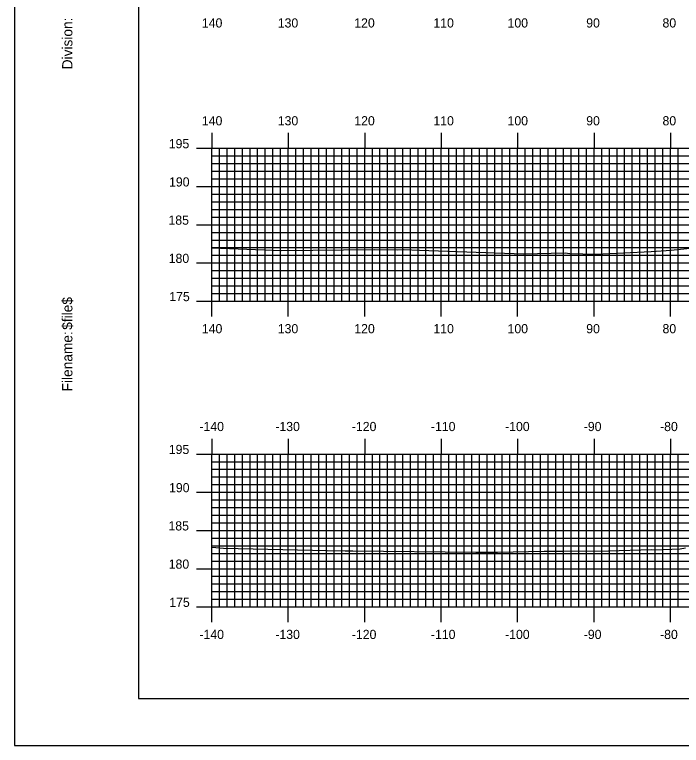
# Model space of a CAD drawing. Extents: x 1823573 to 1823916, y 442591 to 442811.
# Drawn here: x 1823572.5 to 1823659.7, y 442590.5 to 442686.2 of the extents above; entities that cross this region are included whole.
import ezdxf

# ---------------------------------------------------------------- set-up
doc = ezdxf.new("R2010")
doc.units = 0
for name, color, linetype in [('BORDER', 7, 'Continuous'), ('H_V ANNOTATION', 7, 'Continuous'), ('MAJOR', 7, 'Continuous'), ('MINOR', 7, 'Continuous'), ('PLOT BOUNDARY', 7, 'Continuous'), ('S_Roadway_Centerline', 7, 'Continuous')]:
    doc.layers.add(name, color=color, linetype=linetype)

msp = doc.modelspace()

# ---------------------------------------------------------------- linework, layer by layer
at = {"layer": 'BORDER'}
msp.add_lwpolyline([(1823588.709, 442596.665), (1823908.709, 442596.665), (1823908.709, 442806.665), (1823588.709, 442806.665)], close=True, dxfattribs=at)
at = {"layer": 'MAJOR'}
for p, q in [((1823598.309, 442670.669), (1823598.309, 442668.665)), ((1823608.309, 442670.669), (1823608.309, 442668.665)), ((1823618.309, 442670.669), (1823618.309, 442668.665)), ((1823628.309, 442670.669), (1823628.309, 442668.665)), ((1823638.309, 442670.669), (1823638.309, 442668.665)), ((1823648.309, 442670.669), (1823648.309, 442668.665)), ((1823658.309, 442670.669), (1823658.309, 442668.665)), ((1823596.305, 442668.665), (1823598.309, 442668.665)), ((1823598.309, 442668.665), (1823878.309, 442668.665)), ((1823598.309, 442648.665), (1823598.309, 442668.665)), ((1823598.309, 442648.665), (1823598.309, 442668.665)), ((1823598.309, 442668.665), (1823878.309, 442668.665)), ((1823608.309, 442648.665), (1823608.309, 442668.665)), ((1823618.309, 442648.665), (1823618.309, 442668.665)), ((1823628.309, 442648.665), (1823628.309, 442668.665)), ((1823638.309, 442648.665), (1823638.309, 442668.665)), ((1823648.309, 442648.665), (1823648.309, 442668.665)), ((1823658.309, 442648.665), (1823658.309, 442668.665)), ((1823596.305, 442663.665), (1823598.309, 442663.665)), ((1823598.309, 442663.665), (1823878.309, 442663.665)), ((1823596.305, 442658.665), (1823598.309, 442658.665)), ((1823598.309, 442658.665), (1823878.309, 442658.665)), ((1823596.305, 442653.665), (1823598.309, 442653.665)), ((1823598.309, 442653.665), (1823878.309, 442653.665)), ((1823596.305, 442648.665), (1823598.309, 442648.665)), ((1823598.309, 442648.665), (1823878.309, 442648.665)), ((1823598.309, 442648.665), (1823878.309, 442648.665)), ((1823598.309, 442646.661), (1823598.309, 442648.665)), ((1823608.309, 442646.661), (1823608.309, 442648.665)), ((1823618.309, 442646.661), (1823618.309, 442648.665)), ((1823628.309, 442646.661), (1823628.309, 442648.665)), ((1823638.309, 442646.661), (1823638.309, 442648.665)), ((1823648.309, 442646.661), (1823648.309, 442648.665)), ((1823658.309, 442646.661), (1823658.309, 442648.665)), ((1823598.309, 442630.669), (1823598.309, 442628.665)), ((1823608.309, 442630.669), (1823608.309, 442628.665)), ((1823618.309, 442630.669), (1823618.309, 442628.665)), ((1823628.309, 442630.669), (1823628.309, 442628.665)), ((1823638.309, 442630.669), (1823638.309, 442628.665)), ((1823648.309, 442630.669), (1823648.309, 442628.665)), ((1823658.309, 442630.669), (1823658.309, 442628.665)), ((1823596.305, 442628.665), (1823598.309, 442628.665)), ((1823598.309, 442628.665), (1823738.309, 442628.665)), ((1823598.309, 442608.665), (1823598.309, 442628.665)), ((1823598.309, 442608.665), (1823598.309, 442628.665)), ((1823598.309, 442628.665), (1823738.309, 442628.665)), ((1823608.309, 442608.665), (1823608.309, 442628.665)), ((1823618.309, 442608.665), (1823618.309, 442628.665)), ((1823628.309, 442608.665), (1823628.309, 442628.665)), ((1823638.309, 442608.665), (1823638.309, 442628.665)), ((1823648.309, 442608.665), (1823648.309, 442628.665)), ((1823658.309, 442608.665), (1823658.309, 442628.665)), ((1823596.305, 442623.665), (1823598.309, 442623.665)), ((1823598.309, 442623.665), (1823738.309, 442623.665)), ((1823596.305, 442618.665), (1823598.309, 442618.665)), ((1823598.309, 442618.665), (1823738.309, 442618.665)), ((1823596.305, 442613.665), (1823598.309, 442613.665)), ((1823598.309, 442613.665), (1823738.309, 442613.665)), ((1823596.305, 442608.665), (1823598.309, 442608.665)), ((1823598.309, 442608.665), (1823738.309, 442608.665)), ((1823598.309, 442608.665), (1823738.309, 442608.665)), ((1823598.309, 442606.661), (1823598.309, 442608.665)), ((1823608.309, 442606.661), (1823608.309, 442608.665)), ((1823618.309, 442606.661), (1823618.309, 442608.665)), ((1823628.309, 442606.661), (1823628.309, 442608.665)), ((1823638.309, 442606.661), (1823638.309, 442608.665)), ((1823648.309, 442606.661), (1823648.309, 442608.665)), ((1823658.309, 442606.661), (1823658.309, 442608.665))]:
    msp.add_line(p, q, dxfattribs=at)
at = {"layer": 'MINOR'}
for p, q in [((1823599.309, 442648.665), (1823599.309, 442668.665)), ((1823600.309, 442648.665), (1823600.309, 442668.665)), ((1823601.309, 442648.665), (1823601.309, 442668.665)), ((1823602.309, 442648.665), (1823602.309, 442668.665)), ((1823603.309, 442648.665), (1823603.309, 442668.665)), ((1823604.309, 442648.665), (1823604.309, 442668.665)), ((1823605.309, 442648.665), (1823605.309, 442668.665)), ((1823606.309, 442648.665), (1823606.309, 442668.665)), ((1823607.309, 442648.665), (1823607.309, 442668.665)), ((1823609.309, 442648.665), (1823609.309, 442668.665)), ((1823610.309, 442648.665), (1823610.309, 442668.665)), ((1823611.309, 442648.665), (1823611.309, 442668.665)), ((1823612.309, 442648.665), (1823612.309, 442668.665)), ((1823613.309, 442648.665), (1823613.309, 442668.665)), ((1823614.309, 442648.665), (1823614.309, 442668.665)), ((1823615.309, 442648.665), (1823615.309, 442668.665)), ((1823616.309, 442648.665), (1823616.309, 442668.665)), ((1823617.309, 442648.665), (1823617.309, 442668.665)), ((1823619.309, 442648.665), (1823619.309, 442668.665)), ((1823620.309, 442648.665), (1823620.309, 442668.665)), ((1823621.309, 442648.665), (1823621.309, 442668.665)), ((1823622.309, 442648.665), (1823622.309, 442668.665)), ((1823623.309, 442648.665), (1823623.309, 442668.665)), ((1823624.309, 442648.665), (1823624.309, 442668.665)), ((1823625.309, 442648.665), (1823625.309, 442668.665)), ((1823626.309, 442648.665), (1823626.309, 442668.665)), ((1823627.309, 442648.665), (1823627.309, 442668.665)), ((1823629.309, 442648.665), (1823629.309, 442668.665)), ((1823630.309, 442648.665), (1823630.309, 442668.665)), ((1823631.309, 442648.665), (1823631.309, 442668.665)), ((1823632.309, 442648.665), (1823632.309, 442668.665)), ((1823633.309, 442648.665), (1823633.309, 442668.665)), ((1823634.309, 442648.665), (1823634.309, 442668.665)), ((1823635.309, 442648.665), (1823635.309, 442668.665)), ((1823636.309, 442648.665), (1823636.309, 442668.665)), ((1823637.309, 442648.665), (1823637.309, 442668.665)), ((1823639.309, 442648.665), (1823639.309, 442668.665)), ((1823640.309, 442648.665), (1823640.309, 442668.665)), ((1823641.309, 442648.665), (1823641.309, 442668.665)), ((1823642.309, 442648.665), (1823642.309, 442668.665)), ((1823643.309, 442648.665), (1823643.309, 442668.665)), ((1823644.309, 442648.665), (1823644.309, 442668.665)), ((1823645.309, 442648.665), (1823645.309, 442668.665)), ((1823646.309, 442648.665), (1823646.309, 442668.665)), ((1823647.309, 442648.665), (1823647.309, 442668.665)), ((1823649.309, 442648.665), (1823649.309, 442668.665)), ((1823650.309, 442648.665), (1823650.309, 442668.665)), ((1823651.309, 442648.665), (1823651.309, 442668.665)), ((1823652.309, 442648.665), (1823652.309, 442668.665)), ((1823653.309, 442648.665), (1823653.309, 442668.665)), ((1823654.309, 442648.665), (1823654.309, 442668.665)), ((1823655.309, 442648.665), (1823655.309, 442668.665)), ((1823656.309, 442648.665), (1823656.309, 442668.665)), ((1823657.309, 442648.665), (1823657.309, 442668.665)), ((1823659.309, 442648.665), (1823659.309, 442668.665)), ((1823598.309, 442667.665), (1823878.309, 442667.665)), ((1823598.309, 442667.665), (1823600.313, 442667.665)), ((1823598.309, 442666.665), (1823878.309, 442666.665)), ((1823598.309, 442666.665), (1823600.313, 442666.665)), ((1823598.309, 442665.665), (1823878.309, 442665.665)), ((1823598.309, 442665.665), (1823600.313, 442665.665)), ((1823598.309, 442664.665), (1823878.309, 442664.665)), ((1823598.309, 442664.665), (1823600.313, 442664.665)), ((1823598.309, 442662.665), (1823878.309, 442662.665)), ((1823598.309, 442662.665), (1823600.313, 442662.665)), ((1823598.309, 442661.665), (1823878.309, 442661.665)), ((1823598.309, 442661.665), (1823600.313, 442661.665)), ((1823598.309, 442660.665), (1823878.309, 442660.665)), ((1823598.309, 442660.665), (1823600.313, 442660.665)), ((1823598.309, 442659.665), (1823878.309, 442659.665)), ((1823598.309, 442659.665), (1823600.313, 442659.665)), ((1823598.309, 442657.665), (1823878.309, 442657.665)), ((1823598.309, 442657.665), (1823600.313, 442657.665)), ((1823598.309, 442656.665), (1823878.309, 442656.665)), ((1823598.309, 442656.665), (1823600.313, 442656.665)), ((1823598.309, 442655.665), (1823878.309, 442655.665)), ((1823598.309, 442655.665), (1823600.313, 442655.665)), ((1823598.309, 442654.665), (1823878.309, 442654.665)), ((1823598.309, 442654.665), (1823600.313, 442654.665)), ((1823598.309, 442652.665), (1823878.309, 442652.665)), ((1823598.309, 442652.665), (1823600.313, 442652.665)), ((1823598.309, 442651.665), (1823878.309, 442651.665)), ((1823598.309, 442651.665), (1823600.313, 442651.665)), ((1823598.309, 442650.665), (1823878.309, 442650.665)), ((1823598.309, 442650.665), (1823600.313, 442650.665)), ((1823598.309, 442649.665), (1823878.309, 442649.665)), ((1823598.309, 442649.665), (1823600.313, 442649.665)), ((1823599.309, 442608.665), (1823599.309, 442628.665)), ((1823600.309, 442608.665), (1823600.309, 442628.665)), ((1823601.309, 442608.665), (1823601.309, 442628.665)), ((1823602.309, 442608.665), (1823602.309, 442628.665)), ((1823603.309, 442608.665), (1823603.309, 442628.665)), ((1823604.309, 442608.665), (1823604.309, 442628.665)), ((1823605.309, 442608.665), (1823605.309, 442628.665)), ((1823606.309, 442608.665), (1823606.309, 442628.665)), ((1823607.309, 442608.665), (1823607.309, 442628.665)), ((1823609.309, 442608.665), (1823609.309, 442628.665)), ((1823610.309, 442608.665), (1823610.309, 442628.665)), ((1823611.309, 442608.665), (1823611.309, 442628.665)), ((1823612.309, 442608.665), (1823612.309, 442628.665)), ((1823613.309, 442608.665), (1823613.309, 442628.665)), ((1823614.309, 442608.665), (1823614.309, 442628.665)), ((1823615.309, 442608.665), (1823615.309, 442628.665)), ((1823616.309, 442608.665), (1823616.309, 442628.665)), ((1823617.309, 442608.665), (1823617.309, 442628.665)), ((1823619.309, 442608.665), (1823619.309, 442628.665)), ((1823620.309, 442608.665), (1823620.309, 442628.665)), ((1823621.309, 442608.665), (1823621.309, 442628.665)), ((1823622.309, 442608.665), (1823622.309, 442628.665)), ((1823623.309, 442608.665), (1823623.309, 442628.665)), ((1823624.309, 442608.665), (1823624.309, 442628.665)), ((1823625.309, 442608.665), (1823625.309, 442628.665)), ((1823626.309, 442608.665), (1823626.309, 442628.665)), ((1823627.309, 442608.665), (1823627.309, 442628.665)), ((1823629.309, 442608.665), (1823629.309, 442628.665)), ((1823630.309, 442608.665), (1823630.309, 442628.665)), ((1823631.309, 442608.665), (1823631.309, 442628.665)), ((1823632.309, 442608.665), (1823632.309, 442628.665)), ((1823633.309, 442608.665), (1823633.309, 442628.665)), ((1823634.309, 442608.665), (1823634.309, 442628.665)), ((1823635.309, 442608.665), (1823635.309, 442628.665)), ((1823636.309, 442608.665), (1823636.309, 442628.665)), ((1823637.309, 442608.665), (1823637.309, 442628.665)), ((1823639.309, 442608.665), (1823639.309, 442628.665)), ((1823640.309, 442608.665), (1823640.309, 442628.665)), ((1823641.309, 442608.665), (1823641.309, 442628.665)), ((1823642.309, 442608.665), (1823642.309, 442628.665)), ((1823643.309, 442608.665), (1823643.309, 442628.665)), ((1823644.309, 442608.665), (1823644.309, 442628.665)), ((1823645.309, 442608.665), (1823645.309, 442628.665)), ((1823646.309, 442608.665), (1823646.309, 442628.665)), ((1823647.309, 442608.665), (1823647.309, 442628.665)), ((1823649.309, 442608.665), (1823649.309, 442628.665)), ((1823650.309, 442608.665), (1823650.309, 442628.665)), ((1823651.309, 442608.665), (1823651.309, 442628.665)), ((1823652.309, 442608.665), (1823652.309, 442628.665)), ((1823653.309, 442608.665), (1823653.309, 442628.665)), ((1823654.309, 442608.665), (1823654.309, 442628.665)), ((1823655.309, 442608.665), (1823655.309, 442628.665)), ((1823656.309, 442608.665), (1823656.309, 442628.665)), ((1823657.309, 442608.665), (1823657.309, 442628.665)), ((1823659.309, 442608.665), (1823659.309, 442628.665)), ((1823598.309, 442627.665), (1823738.309, 442627.665)), ((1823598.309, 442627.665), (1823600.313, 442627.665)), ((1823598.309, 442626.665), (1823738.309, 442626.665)), ((1823598.309, 442626.665), (1823600.313, 442626.665)), ((1823598.309, 442625.665), (1823738.309, 442625.665)), ((1823598.309, 442625.665), (1823600.313, 442625.665)), ((1823598.309, 442624.665), (1823738.309, 442624.665)), ((1823598.309, 442624.665), (1823600.313, 442624.665)), ((1823598.309, 442622.665), (1823738.309, 442622.665)), ((1823598.309, 442622.665), (1823600.313, 442622.665)), ((1823598.309, 442621.665), (1823738.309, 442621.665)), ((1823598.309, 442621.665), (1823600.313, 442621.665)), ((1823598.309, 442620.665), (1823738.309, 442620.665)), ((1823598.309, 442620.665), (1823600.313, 442620.665)), ((1823598.309, 442619.665), (1823738.309, 442619.665)), ((1823598.309, 442619.665), (1823600.313, 442619.665)), ((1823598.309, 442617.665), (1823738.309, 442617.665)), ((1823598.309, 442617.665), (1823600.313, 442617.665)), ((1823598.309, 442616.665), (1823738.309, 442616.665)), ((1823598.309, 442616.665), (1823600.313, 442616.665)), ((1823598.309, 442615.665), (1823738.309, 442615.665)), ((1823598.309, 442615.665), (1823600.313, 442615.665)), ((1823598.309, 442614.665), (1823738.309, 442614.665)), ((1823598.309, 442614.665), (1823600.313, 442614.665)), ((1823598.309, 442612.665), (1823738.309, 442612.665)), ((1823598.309, 442612.665), (1823600.313, 442612.665)), ((1823598.309, 442611.665), (1823738.309, 442611.665)), ((1823598.309, 442611.665), (1823600.313, 442611.665)), ((1823598.309, 442610.665), (1823738.309, 442610.665)), ((1823598.309, 442610.665), (1823600.313, 442610.665)), ((1823598.309, 442609.665), (1823738.309, 442609.665)), ((1823598.309, 442609.665), (1823600.313, 442609.665))]:
    msp.add_line(p, q, dxfattribs=at)
at = {"layer": 'PLOT BOUNDARY'}
msp.add_lwpolyline([(1823572.522, 442590.547), (1823912.522, 442590.547), (1823912.522, 442810.547), (1823572.522, 442810.547)], close=True, dxfattribs=at)
at = {"layer": 'S_Roadway_Centerline'}
for points in [[(1823598.309, 442655.641), (1823607.465, 442655.311), (1823619.58, 442655.442), (1823622.584, 442655.386), (1823623.446, 442655.407), (1823625.467, 442655.351), (1823639.096, 442654.865), (1823644.515, 442654.988), (1823645.133, 442654.902), (1823648.545, 442654.818), (1823655.765, 442655.182), (1823658.39, 442655.346), (1823664.567, 442656)], [(1823598.309, 442616.474), (1823599.846, 442616.369), (1823613.408, 442616.052), (1823615.748, 442615.992), (1823616.777, 442615.985), (1823632.864, 442615.807), (1823635.692, 442615.806), (1823641.799, 442615.977), (1823644.183, 442615.967), (1823650.204, 442615.999), (1823655.823, 442616.166), (1823656.244, 442616.122), (1823659.583, 442616.261), (1823660.287, 442616.401)]]:
    msp.add_lwpolyline(points, dxfattribs=at)

# ---------------------------------------------------------------- texts
at = {"layer": 'BORDER'}
for s, p in [('Division:', (1823580.078, 442678.997)), ('Division:', (1823580.078, 442678.997)), ('$file$', (1823580.078, 442644.916)), ('$file$', (1823580.078, 442644.916)), ('Filename:', (1823580.078, 442636.862)), ('Filename:', (1823580.078, 442636.862))]:
    msp.add_text(s, height=1.3392, rotation=90, dxfattribs=at).set_placement(p)
at = {"layer": 'H_V ANNOTATION'}
for s, p in [('140', (1823597.014, 442684.465)), ('130', (1823606.939, 442684.465)), ('120', (1823616.949, 442684.465)), ('110', (1823627.292, 442684.465)), ('100', (1823636.992, 442684.465)), ('90', (1823647.281, 442684.465)), ('80', (1823657.259, 442684.465)), ('140', (1823597.014, 442671.665)), ('130', (1823606.939, 442671.665)), ('120', (1823616.949, 442671.665)), ('110', (1823627.292, 442671.665)), ('100', (1823636.992, 442671.665)), ('90', (1823647.281, 442671.665)), ('80', (1823657.259, 442671.665)), ('195', (1823592.686, 442668.665)), ('190', (1823592.718, 442663.665)), ('185', (1823592.643, 442658.665)), ('180', (1823592.675, 442653.665)), ('175', (1823592.75, 442648.665)), ('140', (1823597.014, 442644.465)), ('130', (1823606.939, 442644.465)), ('120', (1823616.949, 442644.465)), ('110', (1823627.292, 442644.465)), ('100', (1823636.992, 442644.465)), ('90', (1823647.281, 442644.465)), ('80', (1823657.259, 442644.465)), ('-140', (1823596.693, 442631.665)), ('-130', (1823606.618, 442631.665)), ('-120', (1823616.628, 442631.665)), ('-110', (1823626.971, 442631.665)), ('-100', (1823636.671, 442631.665)), ('-90', (1823646.96, 442631.665)), ('-80', (1823656.938, 442631.665)), ('195', (1823592.686, 442628.665)), ('190', (1823592.718, 442623.665)), ('185', (1823592.643, 442618.665)), ('180', (1823592.675, 442613.665)), ('175', (1823592.75, 442608.665)), ('-140', (1823596.693, 442604.465)), ('-130', (1823606.618, 442604.465)), ('-120', (1823616.628, 442604.465)), ('-110', (1823626.971, 442604.465)), ('-100', (1823636.671, 442604.465)), ('-90', (1823646.96, 442604.465)), ('-80', (1823656.938, 442604.465))]:
    msp.add_text(s, height=1.2, dxfattribs=at).set_placement(p)
at = {"layer": 'MAJOR'}
for p in [(1823598.3, 442648.665), (1823598.3, 442608.665)]:
    msp.add_text('-', height=0.012, dxfattribs=at).set_placement(p)

doc.saveas('drawing.dxf')
